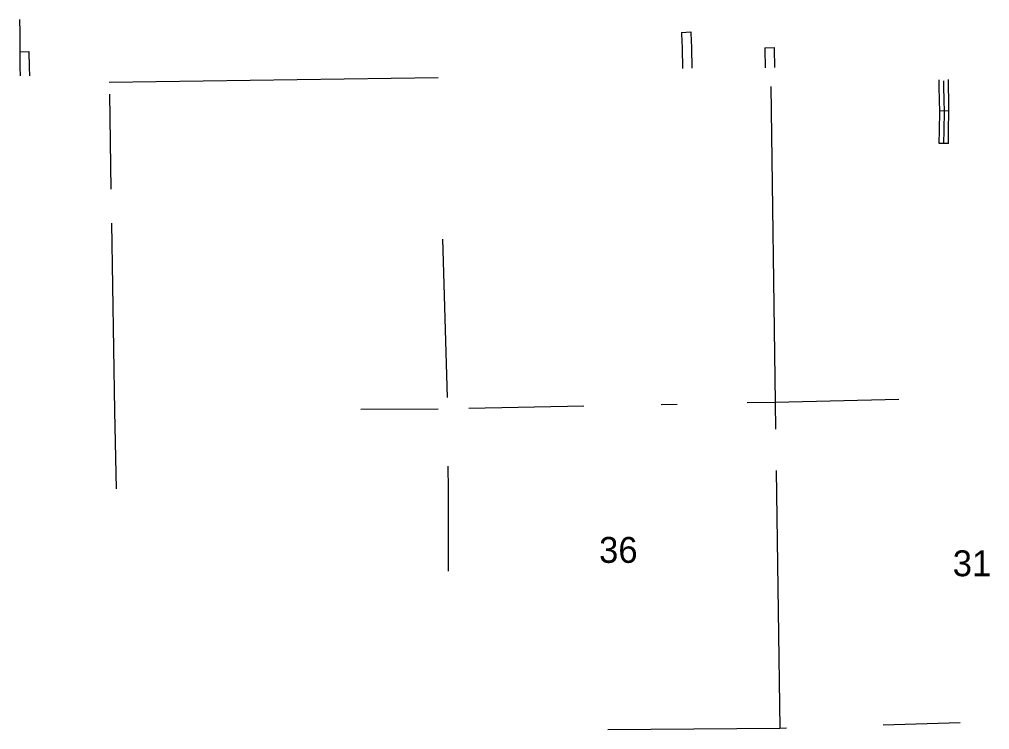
# Model space of a CAD drawing. Extents: x 1127717 to 1741049, y 2026793 to 2244711.
# Drawn here: x 1517042 to 1532860, y 2216439 to 2228023 of the extents above; entities that cross this region are included whole.
import ezdxf

# ---------------------------------------------------------------- set-up
doc = ezdxf.new("R2010")
doc.units = 0
for name, color, linetype in [('32', 7, 'Continuous'), ('4', 7, 'Continuous'), ('5', 7, 'Continuous')]:
    doc.layers.add(name, color=color, linetype=linetype)

msp = doc.modelspace()

# ---------------------------------------------------------------- linework, layer by layer
at = {"layer": '32'}
for p, q in [((1527838, 2227810), (1527988, 2227819)), ((1529197, 2227561), (1529347, 2227564)), ((1517048, 2227496), (1517198, 2227498)), ((1532198, 2226529), (1532048, 2226524)), ((1532189, 2225998), (1532039, 2226000))]:
    msp.add_line(p, q, dxfattribs=at)
for points in [[(1517042, 2228023), (1517047, 2227811), (1517047, 2227556), (1517048, 2227496)], [(1527838, 2227810), (1527839, 2227792), (1527848, 2227554), (1527855, 2227224)], [(1527988, 2227819), (1527989, 2227799), (1527998, 2227558), (1528005, 2227225)], [(1529197, 2227561), (1529197, 2227539), (1529203, 2227235)], [(1529347, 2227564), (1529347, 2227543), (1529353, 2227237)], [(1517048, 2227496), (1517051, 2227242), (1517054, 2227100)], [(1517198, 2227498), (1517201, 2227244), (1517204, 2227103)], [(1532048, 2226524), (1532043, 2226702), (1532039, 2226927), (1532039, 2227038)], [(1532114, 2225999), (1532117, 2226216), (1532123, 2226521), (1532118, 2226703), (1532114, 2226928), (1532114, 2227021)], [(1532198, 2226529), (1532193, 2226705), (1532189, 2226928), (1532189, 2227041)], [(1532039, 2226000), (1532042, 2226217), (1532048, 2226520), (1532048, 2226524)], [(1532189, 2225998), (1532192, 2226214), (1532198, 2226521), (1532198, 2226529)]]:
    msp.add_lwpolyline(points, dxfattribs=at)
at = {"layer": '4'}
for points in [[(1529293, 2226929), (1529362, 2221777), (1529368, 2221342)], [(1529378, 2220667), (1529438, 2216463)], [(1529438, 2216463), (1529547, 2216467)], [(1531123, 2216515), (1532380, 2216554)], [(1526633, 2216439), (1529438, 2216463)]]:
    msp.add_lwpolyline(points, dxfattribs=at)
at = {"layer": '5'}
for points in [[(1518506, 2226998), (1523868, 2227073)], [(1518509, 2226805), (1518534, 2225255)], [(1518543, 2224699), (1518592, 2221633)], [(1523942, 2224437), (1524015, 2221856)], [(1526247, 2221713), (1524369, 2221674)], [(1527767, 2221744), (1527503, 2221738)], [(1529362, 2221777), (1528906, 2221767)], [(1531380, 2221825), (1529362, 2221777)], [(1518592, 2221633), (1518622, 2220364)], [(1523868, 2221666), (1522609, 2221658)], [(1524027, 2220736), (1524030, 2220353), (1524030, 2219022)]]:
    msp.add_lwpolyline(points, dxfattribs=at)

# ---------------------------------------------------------------- texts
for s, p in [('36', (1526493, 2219159)), ('31', (1532259, 2218941))]:
    msp.add_text(s, height=422.4, dxfattribs=at).set_placement(p)

doc.saveas('drawing.dxf')
